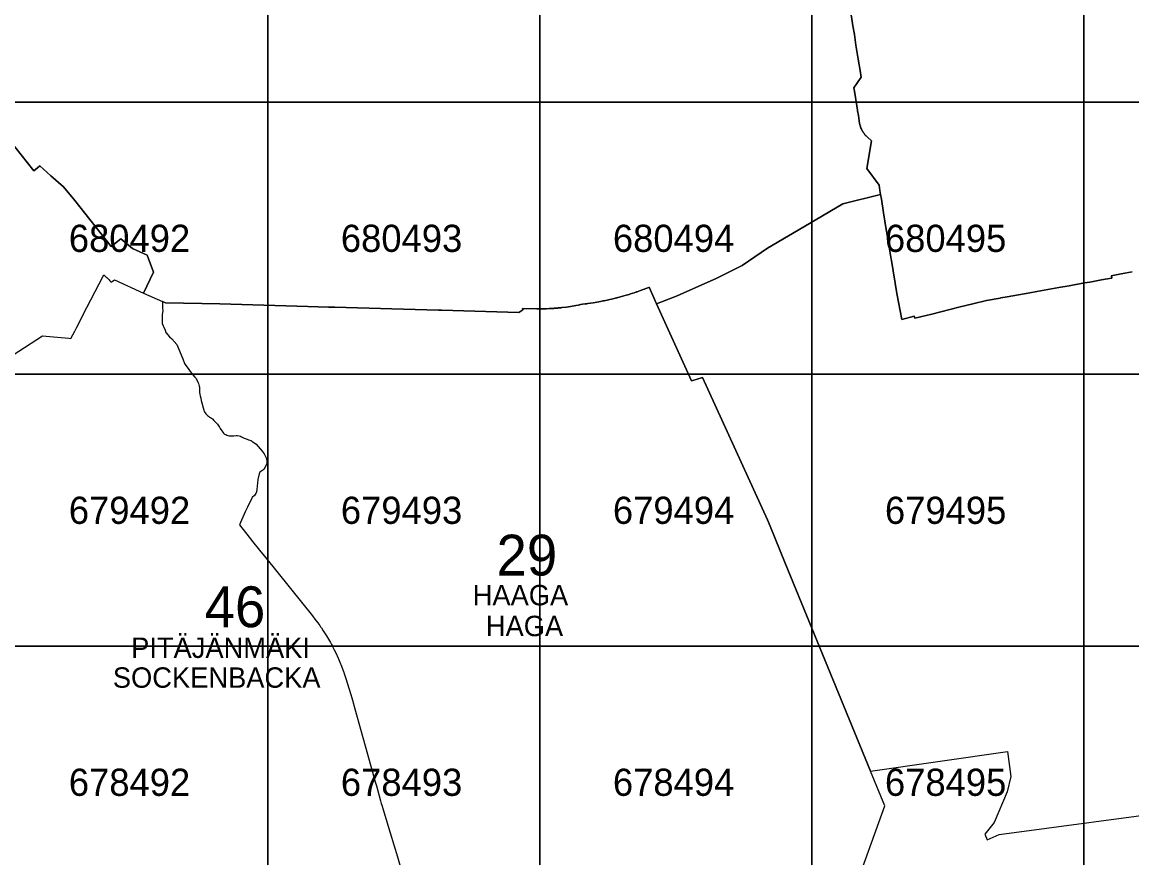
# Model space of a CAD drawing. Extents: x 25485000 to 25520000, y 6656775 to 6690000.
# Drawn here: x 25492097 to 25496176, y 6678222 to 6681295 of the extents above; entities that cross this region are included whole.
import ezdxf

# ---------------------------------------------------------------- set-up
doc = ezdxf.new("R2010")
doc.units = 0
doc.layers.add('Level 63', color=7, linetype='Continuous')

msp = doc.modelspace()

# ---------------------------------------------------------------- linework, layer by layer
at = {"layer": 'Level 63'}
for points in [[(25492000, 6681000), (25493000, 6681000), (25493000, 6682000), (25492000, 6682000)], [(25493000, 6681000), (25494000, 6681000), (25494000, 6682000), (25493000, 6682000)], [(25494000, 6681000), (25495000, 6681000), (25495000, 6682000), (25494000, 6682000)], [(25495000, 6681000), (25496000, 6681000), (25496000, 6682000), (25495000, 6682000)], [(25496000, 6681000), (25497000, 6681000), (25497000, 6682000), (25496000, 6682000)], [(25492000, 6680000), (25493000, 6680000), (25493000, 6681000), (25492000, 6681000)], [(25493000, 6680000), (25494000, 6680000), (25494000, 6681000), (25493000, 6681000)], [(25494000, 6680000), (25495000, 6680000), (25495000, 6681000), (25494000, 6681000)], [(25495000, 6680000), (25496000, 6680000), (25496000, 6681000), (25495000, 6681000)], [(25496000, 6680000), (25497000, 6680000), (25497000, 6681000), (25496000, 6681000)], [(25492000, 6679000), (25493000, 6679000), (25493000, 6680000), (25492000, 6680000)], [(25493000, 6679000), (25494000, 6679000), (25494000, 6680000), (25493000, 6680000)], [(25494000, 6679000), (25495000, 6679000), (25495000, 6680000), (25494000, 6680000)], [(25495000, 6679000), (25496000, 6679000), (25496000, 6680000), (25495000, 6680000)], [(25496000, 6679000), (25497000, 6679000), (25497000, 6680000), (25496000, 6680000)], [(25492000, 6678000), (25493000, 6678000), (25493000, 6679000), (25492000, 6679000)], [(25493000, 6678000), (25494000, 6678000), (25494000, 6679000), (25493000, 6679000)], [(25494000, 6678000), (25495000, 6678000), (25495000, 6679000), (25494000, 6679000)], [(25495000, 6678000), (25496000, 6678000), (25496000, 6679000), (25495000, 6679000)], [(25496000, 6678000), (25497000, 6678000), (25497000, 6679000), (25496000, 6679000)]]:
    msp.add_lwpolyline(points, close=True, dxfattribs=at)
for points in [[(25492046.5, 6680865.7), (25492139.4, 6680748.5), (25492152.8, 6680759.2), (25492161.6, 6680766.1), (25492202.9, 6680729.9), (25492248.7, 6680689.7), (25492290.4, 6680638.6), (25492424.3, 6680469.7), (25492459.3, 6680497.5), (25492502.8, 6680463), (25492556.3, 6680438.1), (25492579.2, 6680375.7), (25492543.1, 6680297.9), (25492612.3, 6680268.2), (25492624.2, 6680263.1), (25492823, 6680258.5), (25493146.7, 6680249.4), (25493223.5, 6680247.2), (25493246.7, 6680246.5), (25493455.6, 6680240.4), (25493627.9, 6680235.7), (25493639.8, 6680235.4), (25493922.4, 6680227.5), (25493937.5, 6680236.6), (25493935.7, 6680241.5), (25493988.5, 6680241.2), (25494024.4, 6680241), (25494034.4, 6680241.4), (25494041.9, 6680241.8), (25494046, 6680242.1), (25494047.1, 6680242.2), (25494048, 6680242.2), (25494049.5, 6680242.3), (25494049.6, 6680242.3), (25494049.8, 6680242.3), (25494050.3, 6680242.4), (25494051.4, 6680242.5), (25494053.1, 6680242.6), (25494060.5, 6680243.2), (25494066.3, 6680243.7), (25494067.6, 6680243.8), (25494068.3, 6680243.9), (25494069.5, 6680244), (25494072.6, 6680244.3), (25494075.7, 6680244.6), (25494078.1, 6680244.9), (25494081.3, 6680245.2), (25494097.4, 6680247.3), (25494113, 6680249.7), (25494131.9, 6680252.9), (25494141.5, 6680254.8), (25494144.9, 6680255.6), (25494146.2, 6680255.8), (25494148.8, 6680256.4), (25494156.7, 6680257.3), (25494166, 6680258.5), (25494172.6, 6680259.4), (25494176.9, 6680260), (25494186.4, 6680261.5), (25494196, 6680263), (25494216.6, 6680266.6), (25494222.8, 6680267.8), (25494232, 6680269.6), (25494236, 6680270.4), (25494252, 6680273.8), (25494268.5, 6680277.7), (25494282.1, 6680281.1), (25494284.7, 6680281.7), (25494287.2, 6680282.4), (25494296.3, 6680284.8), (25494309.2, 6680288.4), (25494317.1, 6680290.7), (25494323.8, 6680292.7), (25494327.7, 6680293.9), (25494332.8, 6680295.5), (25494342.1, 6680298.5), (25494346.8, 6680300), (25494352.8, 6680302), (25494353.2, 6680302.1), (25494353.6, 6680302.3), (25494355.5, 6680302.9), (25494357.2, 6680303.5), (25494369.7, 6680307.9), (25494379.3, 6680311.3), (25494383, 6680312.7), (25494384.6, 6680313.3), (25494389.3, 6680315.1), (25494400.9, 6680319.6), (25494401.2, 6680319.7), (25494401.5, 6680319.8), (25494428.8, 6680259.7), (25494504.8, 6680288.4), (25494650.3, 6680353.5), (25494743.8, 6680400.1), (25494836.5, 6680463.2), (25494991.7, 6680554.4), (25495114, 6680627.1), (25495252.3, 6680661.5), (25495249.9, 6680675.7), (25495246.7, 6680695.1), (25495202.3, 6680756.4), (25495219.7, 6680857.8), (25495203.8, 6680872.3), (25495203, 6680873), (25495200.9, 6680875), (25495198.6, 6680877.3), (25495197.5, 6680878.5), (25495197.1, 6680878.8), (25495196.3, 6680879.7), (25495195.2, 6680881), (25495193.5, 6680883.1), (25495191.7, 6680885.4), (25495191, 6680886.3), (25495190.5, 6680887), (25495190, 6680887.7), (25495189.4, 6680888.6), (25495188.6, 6680889.7), (25495188.2, 6680890.3), (25495187.9, 6680890.8), (25495187.8, 6680891), (25495187.6, 6680891.2), (25495187.4, 6680891.6), (25495187.1, 6680892), (25495186.8, 6680892.5), (25495185.3, 6680895.2), (25495184.4, 6680896.7), (25495183.6, 6680898.2), (25495183.4, 6680898.7), (25495183.1, 6680899.1), (25495182.8, 6680899.8), (25495182.4, 6680900.7), (25495182, 6680901.4), (25495181.8, 6680902), (25495181.4, 6680902.8), (25495181, 6680903.6), (25495180.6, 6680904.5), (25495180.6, 6680904.7), (25495180.5, 6680904.8), (25495180.5, 6680904.8), (25495180.3, 6680905.4), (25495179.7, 6680906.9), (25495179, 6680908.8), (25495178.3, 6680910.6), (25495177.7, 6680912.5), (25495176.9, 6680915), (25495176.2, 6680917.7), (25495175.7, 6680919.6), (25495175.5, 6680920.8), (25495175.3, 6680921.7), (25495175.2, 6680922.3), (25495170.7, 6680951.9), (25495167.9, 6680968.5), (25495167.3, 6680972.3), (25495166.2, 6680978.6), (25495164.9, 6680987.4), (25495156.5, 6681040.7), (25495154.4, 6681052.9), (25495180.8, 6681092.2), (25495179.7, 6681099.2), (25495178.1, 6681109.1), (25495170.1, 6681159.2), (25495162.1, 6681209.9), (25495160.5, 6681219.9), (25495156.1, 6681249.5), (25495150.2, 6681281.1), (25495149.3, 6681289.5), (25495143.9, 6681321.9)], [(25495143.9, 6681321.9), (25495149.3, 6681289.5), (25495150.2, 6681281.1), (25495156.1, 6681249.5), (25495160.5, 6681219.9), (25495162.1, 6681209.9), (25495170.1, 6681159.2), (25495178.1, 6681109.1), (25495179.7, 6681099.2), (25495180.8, 6681092.2), (25495154.4, 6681052.9), (25495156.5, 6681040.7), (25495164.9, 6680987.4), (25495166.2, 6680978.6), (25495167.3, 6680972.3), (25495167.9, 6680968.5), (25495170.7, 6680951.9), (25495175.2, 6680922.3), (25495175.3, 6680921.7), (25495175.5, 6680920.8), (25495175.7, 6680919.6), (25495176.2, 6680917.7), (25495176.9, 6680915), (25495177.7, 6680912.5), (25495178.3, 6680910.6), (25495179, 6680908.8), (25495179.7, 6680906.9), (25495180.3, 6680905.4), (25495180.5, 6680904.8), (25495180.5, 6680904.8), (25495180.6, 6680904.7), (25495180.6, 6680904.5), (25495181, 6680903.6), (25495181.4, 6680902.8), (25495181.8, 6680902), (25495182, 6680901.4), (25495182.4, 6680900.7), (25495182.8, 6680899.8), (25495183.1, 6680899.1), (25495183.4, 6680898.7), (25495183.6, 6680898.2), (25495184.4, 6680896.7), (25495185.3, 6680895.2), (25495186.8, 6680892.5), (25495187.1, 6680892), (25495187.4, 6680891.6), (25495187.6, 6680891.2), (25495187.8, 6680891), (25495187.9, 6680890.8), (25495188.2, 6680890.3), (25495188.6, 6680889.7), (25495189.4, 6680888.6), (25495190, 6680887.7), (25495190.5, 6680887), (25495191, 6680886.3), (25495191.7, 6680885.4), (25495193.5, 6680883.1), (25495195.2, 6680881), (25495196.3, 6680879.7), (25495197.1, 6680878.8), (25495197.5, 6680878.5), (25495198.6, 6680877.3), (25495200.9, 6680875), (25495203, 6680873), (25495203.8, 6680872.3), (25495219.7, 6680857.8), (25495202.3, 6680756.4), (25495246.7, 6680695.1), (25495249.9, 6680675.7), (25495252.3, 6680661.5), (25495255.3, 6680643.4), (25495263.5, 6680594.1), (25495273.6, 6680532.4), (25495274.5, 6680525.7), (25495283.2, 6680474.5), (25495291.6, 6680423.5), (25495292.4, 6680419), (25495312.4, 6680296.9), (25495330.6, 6680201.8), (25495376.5, 6680213.5), (25495378.4, 6680205.8), (25495440.3, 6680221.5), (25495540.4, 6680246.4), (25495591.7, 6680259.2), (25495641.7, 6680271.3), (25495691.7, 6680280.3), (25495694.7, 6680280.8), (25495718, 6680285), (25495738.7, 6680288.7), (25495759.3, 6680292.4), (25495800.7, 6680299.8), (25495827.3, 6680304.5), (25495867.2, 6680311.7), (25495907.2, 6680318.8), (25495945.9, 6680325.8), (25496002.3, 6680335.9), (25496021.1, 6680339.2), (25496058.7, 6680346), (25496077.8, 6680349.4), (25496102.6, 6680353.8), (25496100.8, 6680361.6), (25496100.7, 6680362.2), (25496137, 6680369), (25496176.8, 6680377)], [(25491996.5, 6680029.1), (25492172, 6680141.9), (25492199, 6680139.2), (25492268.2, 6680132.4), (25492275.8, 6680131.7), (25492290.2, 6680158.6), (25492297.8, 6680172.7), (25492315, 6680206.2), (25492320.4, 6680216.9), (25492394.9, 6680360.8), (25492397, 6680364.6), (25492397.9, 6680363.9), (25492400.9, 6680361.8), (25492402.7, 6680360.4), (25492405.1, 6680358.5), (25492407.5, 6680356.5), (25492410, 6680354.3), (25492411.8, 6680352.5), (25492414.3, 6680350), (25492416.5, 6680347.7), (25492419.8, 6680344), (25492422.6, 6680340.5), (25492424.2, 6680338.4), (25492436, 6680347.6), (25492543.1, 6680297.9), (25492579.2, 6680375.7), (25492556.3, 6680438.1), (25492502.8, 6680463), (25492459.3, 6680497.5), (25492424.3, 6680469.7), (25492290.4, 6680638.6), (25492248.7, 6680689.7), (25492202.9, 6680729.9), (25492161.6, 6680766.1), (25492152.8, 6680759.2), (25492139.4, 6680748.5), (25492046.5, 6680865.7)], [(25496176.8, 6680377), (25496137, 6680369), (25496100.7, 6680362.2), (25496100.8, 6680361.6), (25496102.6, 6680353.8), (25496077.8, 6680349.4), (25496058.7, 6680346), (25496021.1, 6680339.2), (25496002.3, 6680335.9), (25495945.9, 6680325.8), (25495907.2, 6680318.8), (25495867.2, 6680311.7), (25495827.3, 6680304.5), (25495800.7, 6680299.8), (25495759.3, 6680292.4), (25495738.7, 6680288.7), (25495718, 6680285), (25495694.7, 6680280.8), (25495691.7, 6680280.3), (25495641.7, 6680271.3), (25495591.7, 6680259.2), (25495540.4, 6680246.4), (25495440.3, 6680221.5), (25495378.4, 6680205.8), (25495376.5, 6680213.5), (25495330.6, 6680201.8), (25495312.4, 6680296.9), (25495292.4, 6680419), (25495291.6, 6680423.5), (25495283.2, 6680474.5), (25495274.5, 6680525.7), (25495273.6, 6680532.4), (25495263.5, 6680594.1), (25495255.3, 6680643.4), (25495252.3, 6680661.5), (25495114, 6680627.1), (25494991.7, 6680554.4), (25494836.5, 6680463.2), (25494743.8, 6680400.1), (25494650.3, 6680353.5), (25494504.8, 6680288.4), (25494428.8, 6680259.7), (25494557.9, 6679976.5), (25494574.3, 6679981.3), (25494598.2, 6679988.3), (25494836.7, 6679464.9), (25494846, 6679442.2), (25494902, 6679305.8), (25495215.7, 6678541.1), (25495718.8, 6678613.4), (25495730.8, 6678521.1), (25495717.9, 6678464.7), (25495669.7, 6678351.7), (25495635.3, 6678309), (25495643.8, 6678288.7), (25495688, 6678307.4), (25496365.4, 6678399)], [(25491996.5, 6680029.1), (25492172, 6680141.9), (25492199, 6680139.2), (25492268.2, 6680132.4), (25492275.8, 6680131.7), (25492290.2, 6680158.6), (25492297.8, 6680172.7), (25492315, 6680206.2), (25492320.4, 6680216.9), (25492394.9, 6680360.8), (25492397, 6680364.6), (25492397.9, 6680363.9), (25492400.9, 6680361.8), (25492402.7, 6680360.4), (25492405.1, 6680358.5), (25492407.5, 6680356.5), (25492410, 6680354.3), (25492411.8, 6680352.5), (25492414.3, 6680350), (25492416.5, 6680347.7), (25492419.8, 6680344), (25492422.6, 6680340.5), (25492424.2, 6680338.4), (25492436, 6680347.6), (25492543.1, 6680297.9), (25492612.3, 6680268.2), (25492612.5, 6680263.3), (25492612.3, 6680251.7), (25492612.8, 6680241.7), (25492613.9, 6680234.7), (25492611.2, 6680219.2), (25492611.1, 6680212.7), (25492611.9, 6680202.7), (25492611.7, 6680194.2), (25492612.2, 6680186.2), (25492614.7, 6680178.7), (25492618.2, 6680172.7), (25492622.7, 6680162.5), (25492624.9, 6680154.2), (25492638.1, 6680137.9), (25492646.6, 6680130.5), (25492665.6, 6680109.2), (25492687.6, 6680056.9), (25492694.2, 6680039.4), (25492698.2, 6680032.1), (25492703.1, 6680026.1), (25492718, 6680005.1), (25492724.7, 6679997.6), (25492732, 6679989.7), (25492734.8, 6679986.3), (25492736.7, 6679983.6), (25492738.6, 6679979.8), (25492742.6, 6679971.6), (25492744.9, 6679966.2), (25492746.3, 6679961.7), (25492747.7, 6679956.9), (25492748.5, 6679952.4), (25492748.6, 6679948), (25492748.5, 6679939.2), (25492748.7, 6679933.7), (25492750, 6679925.5), (25492750.9, 6679921.4), (25492753.4, 6679911.7), (25492755.4, 6679903.2), (25492757.5, 6679894.5), (25492762.3, 6679877), (25492764.7, 6679868.5), (25492766.4, 6679863.2), (25492769.3, 6679858.3), (25492772.1, 6679854.7), (25492775.3, 6679851.5), (25492778.4, 6679848), (25492782, 6679845.5), (25492786.1, 6679842.6), (25492789.4, 6679840.6), (25492796.2, 6679835.8), (25492801.7, 6679830.3), (25492814.6, 6679816.3), (25492821.8, 6679805.7), (25492824.7, 6679800.2), (25492830.7, 6679791.7), (25492834.4, 6679786.9), (25492837.3, 6679783), (25492841.1, 6679780.5), (25492845.8, 6679778.7), (25492849.4, 6679776.6), (25492853.4, 6679775), (25492857.8, 6679773.7), (25492861.4, 6679773.4), (25492869.8, 6679773.7), (25492875.1, 6679774.2), (25492883.9, 6679774.9), (25492888.8, 6679775.1), (25492894.5, 6679774.1), (25492899.1, 6679772.5), (25492903.6, 6679770.5), (25492908.1, 6679768.2), (25492912.6, 6679765.5), (25492917.2, 6679763.4), (25492924.4, 6679761.2), (25492928.9, 6679759.1), (25492933.8, 6679758.3), (25492937.5, 6679756.9), (25492939.5, 6679755.7), (25492940.8, 6679754.7), (25492945.4, 6679751.1), (25492956.6, 6679742.8), (25492979.8, 6679717.8), (25492986.4, 6679707.8), (25492994.5, 6679692.3), (25492996.9, 6679684.3), (25492996.1, 6679671.5), (25492990.8, 6679658.3), (25492985.8, 6679649.8), (25492971.2, 6679640.3), (25492968.3, 6679634.3), (25492963.5, 6679612.8), (25492960.2, 6679576.8), (25492958.9, 6679568.3), (25492956.1, 6679561.8), (25492950.9, 6679554.8), (25492941.9, 6679546.6), (25492941, 6679544.7), (25492925.5, 6679512), (25492918.4, 6679496.3), (25492903.8, 6679463.6), (25492895.3, 6679446.5), (25492931.7, 6679401.6), (25492943.7, 6679385.6), (25492969.8, 6679353.6), (25492992.4, 6679325.6), (25493124, 6679161.6), (25493164.2, 6679111.6), (25493173.2, 6679100.1), (25493183.8, 6679086), (25493190.9, 6679076.1), (25493194.2, 6679071.3), (25493196.9, 6679067.3), (25493203.9, 6679056.8), (25493215.2, 6679039), (25493229.9, 6679014), (25493233.7, 6679007), (25493236, 6679002.8), (25493239.1, 6678996.9), (25493243.9, 6678987.5), (25493249.9, 6678975.3), (25493258.6, 6678956), (25493259.6, 6678954.2), (25493265, 6678941.3), (25493270.7, 6678927.2), (25493275.7, 6678913.8), (25493277.9, 6678907.8), (25493278.9, 6678905.1), (25493279.3, 6678904), (25493281.9, 6678896.3), (25493284.5, 6678888.4), (25493285.4, 6678885.6), (25493305.7, 6678822.9), (25493311.5, 6678802.2), (25493320.4, 6678769.9), (25493329, 6678739.1), (25493341, 6678695.8), (25493366.7, 6678603.3), (25493394.9, 6678501.6), (25493398.9, 6678487.1), (25493414.5, 6678431.2), (25493416.9, 6678422.5), (25493418.8, 6678416.1), (25493449.6, 6678313.9), (25493476.1, 6678226.4), (25493486.4, 6678192)], [(25495054.3, 6677820.9), (25495268.2, 6678413.1), (25495215.7, 6678541.1), (25494902, 6679305.8), (25494846, 6679442.2), (25494836.7, 6679464.9), (25494598.2, 6679988.3), (25494574.3, 6679981.3), (25494557.9, 6679976.5), (25494428.8, 6680259.7), (25494401.5, 6680319.8), (25494401.2, 6680319.7), (25494400.9, 6680319.6), (25494389.3, 6680315.1), (25494384.6, 6680313.3), (25494383, 6680312.7), (25494379.3, 6680311.3), (25494369.7, 6680307.9), (25494357.2, 6680303.5), (25494355.5, 6680302.9), (25494353.6, 6680302.3), (25494353.2, 6680302.1), (25494352.8, 6680302), (25494346.8, 6680300), (25494342.1, 6680298.5), (25494332.8, 6680295.5), (25494327.7, 6680293.9), (25494323.8, 6680292.7), (25494317.1, 6680290.7), (25494309.2, 6680288.4), (25494296.3, 6680284.8), (25494287.2, 6680282.4), (25494284.7, 6680281.7), (25494282.1, 6680281.1), (25494268.5, 6680277.7), (25494252, 6680273.8), (25494236, 6680270.4), (25494232, 6680269.6), (25494222.8, 6680267.8), (25494216.6, 6680266.6), (25494196, 6680263), (25494186.4, 6680261.5), (25494176.9, 6680260), (25494172.6, 6680259.4), (25494166, 6680258.5), (25494156.7, 6680257.3), (25494148.8, 6680256.4), (25494146.2, 6680255.8), (25494144.9, 6680255.6), (25494141.5, 6680254.8), (25494131.9, 6680252.9), (25494113, 6680249.7), (25494097.4, 6680247.3), (25494081.3, 6680245.2), (25494078.1, 6680244.9), (25494075.7, 6680244.6), (25494072.6, 6680244.3), (25494069.5, 6680244), (25494068.3, 6680243.9), (25494067.6, 6680243.8), (25494066.3, 6680243.7), (25494060.5, 6680243.2), (25494053.1, 6680242.6), (25494051.4, 6680242.5), (25494050.3, 6680242.4), (25494049.8, 6680242.3), (25494049.6, 6680242.3), (25494049.5, 6680242.3), (25494048, 6680242.2), (25494047.1, 6680242.2), (25494046, 6680242.1), (25494041.9, 6680241.8), (25494034.4, 6680241.4), (25494024.4, 6680241), (25493988.5, 6680241.2), (25493935.7, 6680241.5), (25493937.5, 6680236.6), (25493922.4, 6680227.5), (25493639.8, 6680235.4), (25493627.9, 6680235.7), (25493455.6, 6680240.4), (25493246.7, 6680246.5), (25493223.5, 6680247.2), (25493146.7, 6680249.4), (25492823, 6680258.5), (25492624.2, 6680263.1), (25492612.3, 6680268.2)], [(25492612.3, 6680268.2), (25492612.5, 6680263.3), (25492612.3, 6680251.7), (25492612.8, 6680241.7), (25492613.9, 6680234.7), (25492611.2, 6680219.2), (25492611.1, 6680212.7), (25492611.9, 6680202.7), (25492611.7, 6680194.2), (25492612.2, 6680186.2), (25492614.7, 6680178.7), (25492618.2, 6680172.7), (25492622.7, 6680162.5), (25492624.9, 6680154.2), (25492638.1, 6680137.9), (25492646.6, 6680130.5), (25492665.6, 6680109.2), (25492687.6, 6680056.9), (25492694.2, 6680039.4), (25492698.2, 6680032.1), (25492703.1, 6680026.1), (25492718, 6680005.1), (25492724.7, 6679997.6), (25492732, 6679989.7), (25492734.8, 6679986.3), (25492736.7, 6679983.6), (25492738.6, 6679979.8), (25492742.6, 6679971.6), (25492744.9, 6679966.2), (25492746.3, 6679961.7), (25492747.7, 6679956.9), (25492748.5, 6679952.4), (25492748.6, 6679948), (25492748.5, 6679939.2), (25492748.7, 6679933.7), (25492750, 6679925.5), (25492750.9, 6679921.4), (25492753.4, 6679911.7), (25492755.4, 6679903.2), (25492757.5, 6679894.5), (25492762.3, 6679877), (25492764.7, 6679868.5), (25492766.4, 6679863.2), (25492769.3, 6679858.3), (25492772.1, 6679854.7), (25492775.3, 6679851.5), (25492778.4, 6679848), (25492782, 6679845.5), (25492786.1, 6679842.6), (25492789.4, 6679840.6), (25492796.2, 6679835.8), (25492801.7, 6679830.3), (25492814.6, 6679816.3), (25492821.8, 6679805.7), (25492824.7, 6679800.2), (25492830.7, 6679791.7), (25492834.4, 6679786.9), (25492837.3, 6679783), (25492841.1, 6679780.5), (25492845.8, 6679778.7), (25492849.4, 6679776.6), (25492853.4, 6679775), (25492857.8, 6679773.7), (25492861.4, 6679773.4), (25492869.8, 6679773.7), (25492875.1, 6679774.2), (25492883.9, 6679774.9), (25492888.8, 6679775.1), (25492894.5, 6679774.1), (25492899.1, 6679772.5), (25492903.6, 6679770.5), (25492908.1, 6679768.2), (25492912.6, 6679765.5), (25492917.2, 6679763.4), (25492924.4, 6679761.2), (25492928.9, 6679759.1), (25492933.8, 6679758.3), (25492937.5, 6679756.9), (25492939.5, 6679755.7), (25492940.8, 6679754.7), (25492945.4, 6679751.1), (25492956.6, 6679742.8), (25492979.8, 6679717.8), (25492986.4, 6679707.8), (25492994.5, 6679692.3), (25492996.9, 6679684.3), (25492996.1, 6679671.5), (25492990.8, 6679658.3), (25492985.8, 6679649.8), (25492971.2, 6679640.3), (25492968.3, 6679634.3), (25492963.5, 6679612.8), (25492960.2, 6679576.8), (25492958.9, 6679568.3), (25492956.1, 6679561.8), (25492950.9, 6679554.8), (25492941.9, 6679546.6), (25492941, 6679544.7), (25492925.5, 6679512), (25492918.4, 6679496.3), (25492903.8, 6679463.6), (25492895.3, 6679446.5), (25492931.7, 6679401.6), (25492943.7, 6679385.6), (25492969.8, 6679353.6), (25492992.4, 6679325.6), (25493124, 6679161.6), (25493164.2, 6679111.6), (25493173.2, 6679100.1), (25493183.8, 6679086), (25493190.9, 6679076.1), (25493194.2, 6679071.3), (25493196.9, 6679067.3), (25493203.9, 6679056.8), (25493215.2, 6679039), (25493229.9, 6679014), (25493233.7, 6679007), (25493236, 6679002.8), (25493239.1, 6678996.9), (25493243.9, 6678987.5), (25493249.9, 6678975.3), (25493258.6, 6678956), (25493259.6, 6678954.2), (25493265, 6678941.3), (25493270.7, 6678927.2), (25493275.7, 6678913.8), (25493277.9, 6678907.8), (25493278.9, 6678905.1), (25493279.3, 6678904), (25493281.9, 6678896.3), (25493284.5, 6678888.4), (25493285.4, 6678885.6), (25493305.7, 6678822.9), (25493311.5, 6678802.2), (25493320.4, 6678769.9), (25493329, 6678739.1), (25493341, 6678695.8), (25493366.7, 6678603.3), (25493394.9, 6678501.6), (25493398.9, 6678487.1), (25493414.5, 6678431.2), (25493416.9, 6678422.5), (25493418.8, 6678416.1), (25493449.6, 6678313.9), (25493476.1, 6678226.4), (25493486.4, 6678192)], [(25494930, 6677273.2), (25494873.2, 6677319.8), (25495041.5, 6677785.5), (25495054.3, 6677820.9), (25495268.2, 6678413.1), (25495215.7, 6678541.1), (25495718.8, 6678613.4), (25495730.8, 6678521.1), (25495717.9, 6678464.7), (25495669.7, 6678351.7), (25495635.3, 6678309), (25495643.8, 6678288.7), (25495688, 6678307.4), (25496365.4, 6678399)]]:
    msp.add_lwpolyline(points, dxfattribs=at)

# ---------------------------------------------------------------- texts
for s, height, p in [('680492', 100, (25492268.5, 6680450)), ('680493', 100, (25493268.5, 6680450)), ('680494', 100, (25494268.5, 6680450)), ('680495', 100, (25495268.5, 6680450)), ('679492', 100, (25492268.5, 6679450)), ('679493', 100, (25493268.5, 6679450)), ('679494', 100, (25494268.5, 6679450)), ('679495', 100, (25495268.5, 6679450)), ('29', 150, (25493840.7, 6679260.2)), ('46', 150, (25492767.7, 6679070.2)), ('HAAGA', 75, (25493753.1, 6679150.5)), ('HAGA', 75, (25493801.5, 6679037.2)), ('PITÄJÄNMÄKI', 75, (25492497.5, 6678957.1)), ('SOCKENBACKA', 75, (25492430.3, 6678847.5)), ('678492', 100, (25492268.5, 6678450)), ('678493', 100, (25493268.5, 6678450)), ('678494', 100, (25494268.5, 6678450)), ('678495', 100, (25495268.5, 6678450))]:
    msp.add_text(s, height=height, dxfattribs=at).set_placement(p)

doc.saveas('drawing.dxf')
